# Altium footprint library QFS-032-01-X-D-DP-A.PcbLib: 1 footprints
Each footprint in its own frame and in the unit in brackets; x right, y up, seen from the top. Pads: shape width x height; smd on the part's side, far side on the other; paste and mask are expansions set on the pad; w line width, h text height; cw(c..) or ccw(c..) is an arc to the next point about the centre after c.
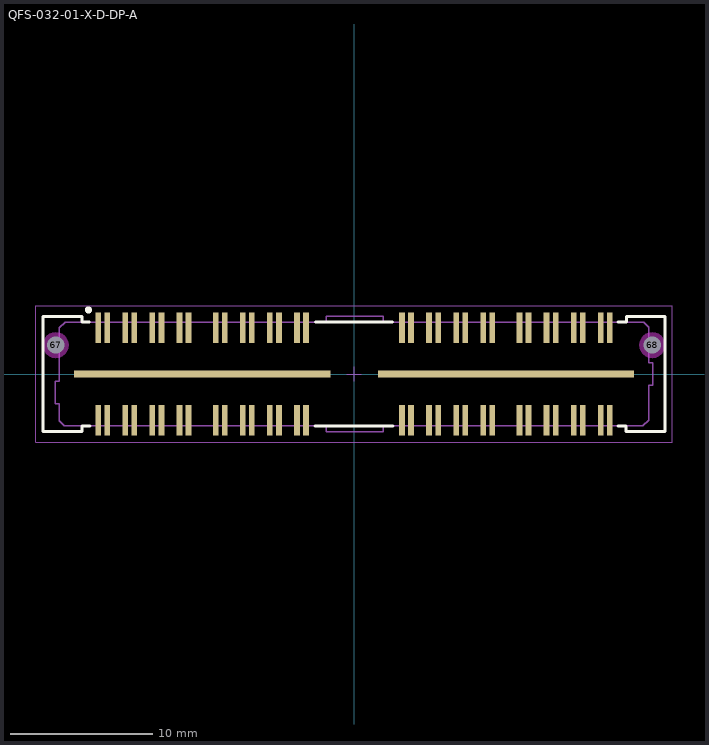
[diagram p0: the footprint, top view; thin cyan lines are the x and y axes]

## QFS-032-01-X-D-DP-A [mm] "0.635mm pitch, 64 pin, rugged high speed socket; differential"
height 7.06
pads (68):
  rect 0.4x2.15 smd mask+0: 1(-17.972,3.24) 2(-17.972,-3.24) 3(-17.337,3.24) 4(-17.337,-3.24) 5(-16.067,3.24) 6(-16.067,-3.24) 7(-15.432,3.24) 8(-15.432,-3.24) 9(-14.162,3.24) 10(-14.162,-3.24) 11(-13.527,3.24) 12(-13.527,-3.24) 13(-12.257,3.24) 14(-12.257,-3.24) 15(-11.622,3.24) 16(-11.622,-3.24) 17(-9.717,3.24) 18(-9.717,-3.24) 19(-9.082,3.24) 20(-9.082,-3.24) 21(-7.812,3.24) 22(-7.812,-3.24) 23(-7.177,3.24) 24(-7.177,-3.24) 25(-5.907,3.24) 26(-5.907,-3.24) 27(-5.272,3.24) 28(-5.272,-3.24) 29(-4.002,3.24) 30(-4.002,-3.24) 31(-3.367,3.24) 32(-3.367,-3.24) 33(3.368,3.24) 34(3.368,-3.24) 35(4.003,3.24) 36(4.003,-3.24) 37(5.273,3.24) 38(5.273,-3.24) 39(5.908,3.24) 40(5.908,-3.24) 41(7.178,3.24) 42(7.178,-3.24) 43(7.813,3.24) 44(7.813,-3.24) 45(9.083,3.24) 46(9.083,-3.24) 47(9.718,3.24) 48(9.718,-3.24) 49(11.623,3.24) 50(11.623,-3.24) 51(12.258,3.24) 52(12.258,-3.24) 53(13.528,3.24) 54(13.528,-3.24) 55(14.163,3.24) 56(14.163,-3.24) 57(15.433,3.24) 58(15.433,-3.24) 59(16.068,3.24) 60(16.068,-3.24) 61(17.338,3.24) 62(17.338,-3.24) 63(17.973,3.24) 64(17.973,-3.24)
  rect 18x0.5 smd mask+0: 65(-10.667,0) 66(10.673,0)
  round 1 hole 1.2 unplated mask+0: 67(-20.947,2.03) 68(20.953,2.03)
Top Overlay:
  circle w0.25: c-18.65,4.5 r0.125
  lines w0.2: -18.6,3.65 -19.1,3.65 -19.1,4.05 -21.85,4.05 -21.85,-4.05 -19.1,-4.05 -19.1,-3.65 -18.55,-3.65 ; -2.75,-3.65 2.75,-3.65 ; -2.7,3.65 2.7,3.65 ; 18.55,-3.65 19.1,-3.65 19.1,-4.05 21.85,-4.05 21.85,4.05 19.15,4.05 19.15,3.65 18.55,3.65
Keep-Out Layer:
  pour cut-out: -20.04,2.03 -20.07,2.265 -20.161,2.484 -20.305,2.672 -20.493,2.816 -20.712,2.907 -20.947,2.938 -21.182,2.907 -21.401,2.816 -21.589,2.672 -21.733,2.484 -21.824,2.265 -21.855,2.03 -21.824,1.795 -21.733,1.576 -21.589,1.388 -21.401,1.244 -21.182,1.153 -20.947,1.122 -20.712,1.153 -20.493,1.244 -20.305,1.388 -20.161,1.576 -20.07,1.795
  pour cut-out: 21.86,2.03 21.83,2.265 21.739,2.484 21.595,2.672 21.407,2.816 21.188,2.907 20.953,2.938 20.718,2.907 20.499,2.816 20.311,2.672 20.167,2.484 20.076,2.265 20.045,2.03 20.076,1.795 20.167,1.576 20.311,1.388 20.499,1.244 20.718,1.153 20.953,1.122 21.188,1.153 21.407,1.244 21.595,1.388 21.739,1.576 21.83,1.795
Mechanical 12:
  lines w0.001: -21.85,-4.05 -21.85,4.05 -19.1,4.05 -19.1,3.65 -1.95,3.65 -1.95,4.05 2.05,4.05 2.05,3.65 19.15,3.65 19.15,4.05 21.85,4.05 21.85,-4.05 19.1,-4.05 19.1,-3.65 2.05,-3.65 2.05,-4.05 -1.95,-4.05 -1.95,-3.65 -19.1,-3.65 -19.1,-4.05 -21.85,-4.05
Mechanical 13:
  lines w0.1: -19.1,-3.65 -19.1,-4.05 -21.85,-4.05 -21.85,4.05 -19.1,4.05 -19.1,3.65 ; -1.95,-3.65 -1.95,-4.05 2.05,-4.05 2.05,-3.65 ; -1.95,3.65 -1.95,4.05 2.05,4.05 2.05,3.65 ; 19.1,-3.65 19.1,-4.05 21.85,-4.05 21.85,4.05 19.15,4.05 19.15,3.65 ; -21,-2.1 -20.7,-2.1 -20.7,-3.3 -20.35,-3.65 20.3,-3.65 20.7,-3.25 20.7,-0.8 21,-0.8 21,0.8 20.7,0.8 20.7,3.3 20.35,3.65 -20.3,3.65 -20.7,3.25 -20.7,-0.5 -21,-0.5 -21,-2.1
  text ".Designator" at 0.254,0.254 h1.52
Mechanical 15:
  lines w0.05: -0.5,0 0.5,0 ; 0,-0.5 0,0.5 ; -22.35,-4.8 -22.35,4.8 22.35,4.8 22.35,-4.8 -22.35,-4.8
